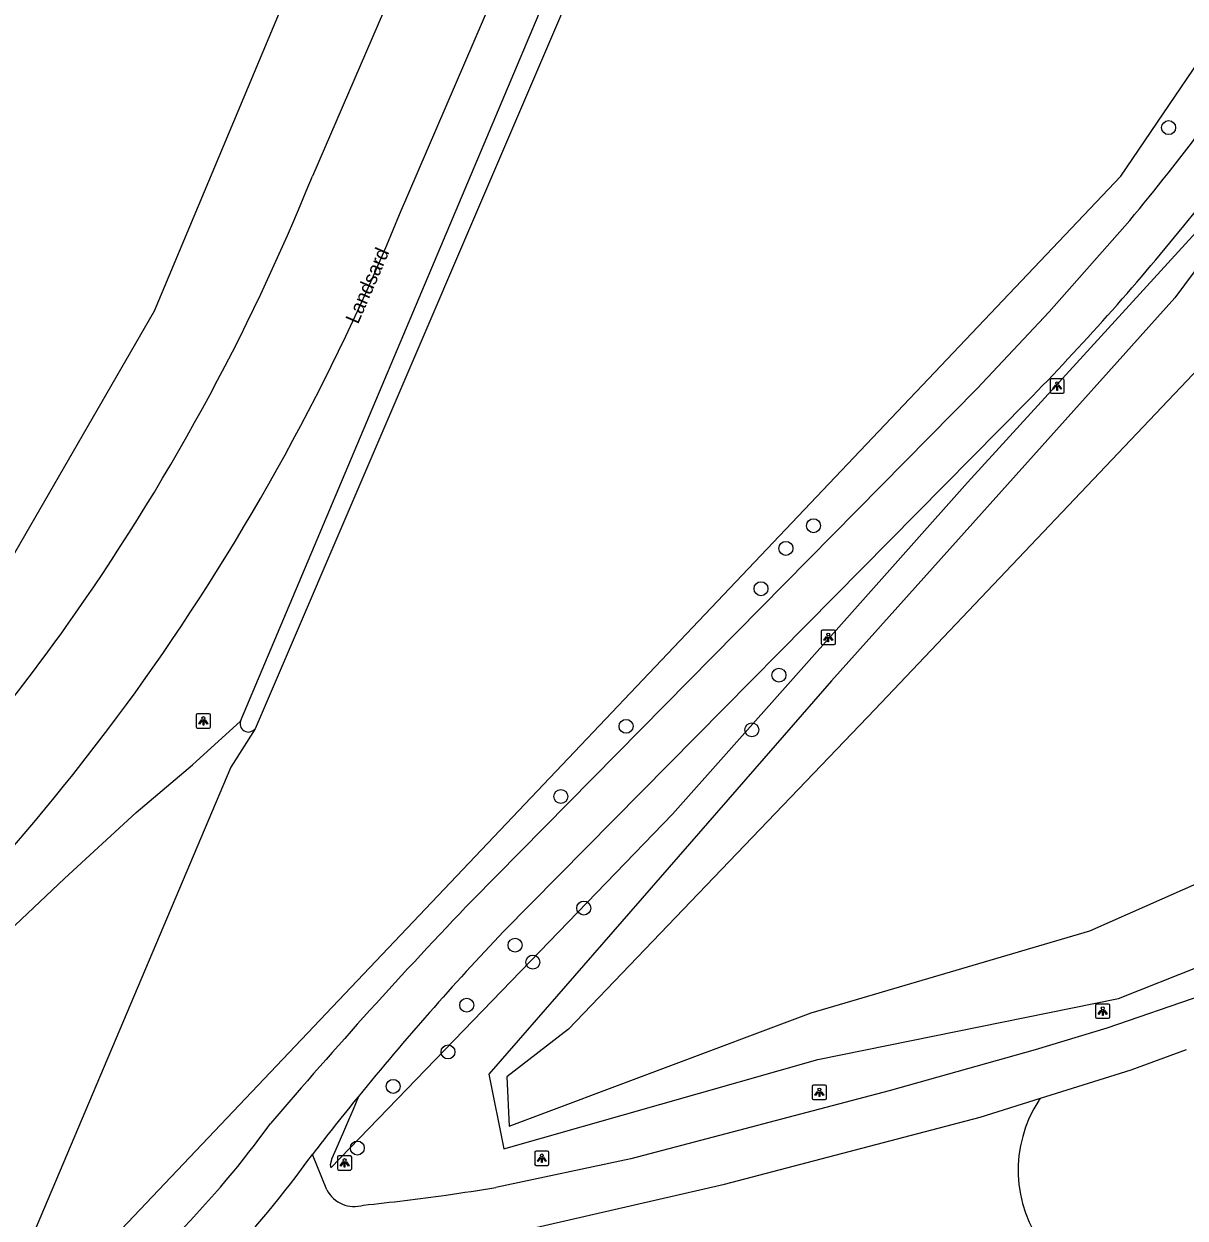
# Model space of a CAD drawing. Extents: x 155209 to 156823, y 385356 to 388482.
# Drawn here: x 155855.7 to 155937, y 385809.7 to 385893.3 of the extents above; entities that cross this region are included whole.
import ezdxf

# ---------------------------------------------------------------- set-up
doc = ezdxf.new("R2010")
doc.units = 0
for name, color, linetype in [('IMGEO_Berm_groen', 7, 'Continuous'), ('IMGEO_Boom', 7, 'Continuous'), ('IMGEO_Fietspad_gesloten', 7, 'Continuous'), ('IMGEO_Gemengd_bos', 7, 'Continuous'), ('IMGEO_Groenvoorziening', 7, 'Continuous'), ('IMGEO_Lichtpunt', 7, 'Continuous'), ('IMGEO_Meer_plas_ven_vijver', 7, 'Continuous'), ('IMGEO_Openbare_ruimte_label', 7, 'Continuous'), ('IMGEO_Rijbaan_lokaal_gesloten', 7, 'Continuous'), ('IMGEO_Voetpad_gesloten', 7, 'Continuous'), ('IMGEO_Waterloop', 7, 'Continuous')]:
    doc.layers.add(name, color=color, linetype=linetype)

msp = doc.modelspace()

# ---------------------------------------------------------------- linework, layer by layer
at = {"layer": 'IMGEO_Berm_groen'}
for points in [[(155912.875, 385986.207), (155891.584, 385937.043), (155864.833, 385873.201), (155853.128, 385852.94), (155810.491, 385814.255)], [(155851.64, 385797.46), (155932.5, 385882.64), (155974.754, 385944.878)], [(155879.138, 385818.21), (155878.761, 385817.288), (155878.446, 385816.541), (155878.095, 385815.729), (155877.542, 385814.495), (155877.266, 385813.848), (155877.158, 385813.41), (155877.205, 385813.205), (155901.117, 385837.978), (155921.768, 385861.187), (155942.453, 385883.841), (155948.49, 385892.599), (155963.233, 385915.282), (155979.151, 385938.711)]]:
    msp.add_lwpolyline(points, dxfattribs=at)
at = {"layer": 'IMGEO_Boom'}
for centre in [(155935.858, 385886.043), (155910.998, 385858.168), (155909.063, 385856.581), (155907.318, 385853.758), (155908.575, 385847.699), (155897.871, 385844.121), (155906.676, 385843.871), (155893.306, 385839.208), (155894.908, 385831.395), (155890.1, 385828.798), (155891.34, 385827.613), (155886.714, 385824.599), (155885.405, 385821.32), (155881.565, 385818.91), (155879.058, 385814.591)]:
    msp.add_circle(centre, 0.489, dxfattribs=at)
at = {"layer": 'IMGEO_Fietspad_gesloten'}
for points in [[(155933.141, 385879.54), (155927.488, 385873.153), (155922.459, 385867.783), (155887.111, 385831.956)], [(155889.293, 385829.761), (155925.96, 385866.867)]]:
    msp.add_lwpolyline(points, dxfattribs=at)
for centre, radius, start, end in [((155776.139, 386009.099), 203.556, 320.47045, 325.2588), ((155816.957, 385978.333), 155.642, 320.42192, 326.01192), ((155802.683, 385987.718), 172.634, 315.5693, 321.03944), ((156157.898, 385573.198), 374.541, 136.30132, 139.52582), ((156039.362, 385687.589), 206.721, 136.54794, 140.81176), ((156023.94, 385699.941), 186.963, 140.75915, 142.35172), ((155818.09, 385855.945), 67.705, 307.10906, 324.17353), ((155820.492, 385853.717), 68.097, 307.27808, 324.46586)]:
    msp.add_arc(centre, radius, start, end, dxfattribs=at)
at = {"layer": 'IMGEO_Gemengd_bos'}
for points in [[(155783.189, 385764.802), (155786.452, 385768.755), (155814.49, 385793.571), (155841.441, 385817.507), (155847.372, 385823.232), (155851.615, 385826.935), (155858.565, 385833.471), (155863.57, 385838.094), (155867.526, 385841.417), (155870.87, 385844.477)], [(155871.899, 385843.955), (155870.192, 385841.27), (155853.466, 385801.772)]]:
    msp.add_lwpolyline(points, dxfattribs=at)
at = {"layer": 'IMGEO_Groenvoorziening'}
for points in [[(155888.261, 385819.766), (155889.317, 385814.546), (155911.288, 385820.799), (155932.355, 385825.067), (155949.646, 385831.927), (155967.557, 385842.808), (155981.858, 385856.223), (155994.392, 385870.487), (156007.087, 385887.004), (156010.242, 385891.845), (156009.128, 385895.281), (155991.836, 385915.751), (155977.796, 385930.252), (155955.115, 385899.464), (155936.283, 385874.129), (155912.245, 385847.299), (155888.261, 385819.766)], [(155926.885, 385818.084), (155926.778, 385817.932)]]:
    msp.add_lwpolyline(points, dxfattribs=at)
for centre, radius, start, end in [((155934.165, 385813.062), 8.897, 244.03812, 60.4661), ((155934.257, 385813.045), 8.934, 146.84109, 217.45408)]:
    msp.add_arc(centre, radius, start, end, dxfattribs=at)
at = {"layer": 'IMGEO_Lichtpunt'}
for p, q in [((155927.555, 385868.35), (155927.555, 385867.543)), ((155927.555, 385868.35), (155927.555, 385867.543)), ((155928.457, 385868.445), (155927.649, 385868.445)), ((155928.457, 385868.445), (155927.649, 385868.445)), ((155928.551, 385867.543), (155928.551, 385868.35)), ((155928.551, 385867.543), (155928.551, 385868.35)), ((155927.649, 385867.449), (155928.457, 385867.449)), ((155927.649, 385867.449), (155928.457, 385867.449)), ((155911.532, 385850.753), (155911.532, 385849.946)), ((155911.532, 385850.753), (155911.532, 385849.946)), ((155912.434, 385850.848), (155911.626, 385850.848)), ((155912.434, 385850.848), (155911.626, 385850.848)), ((155912.528, 385849.946), (155912.528, 385850.753)), ((155912.528, 385849.946), (155912.528, 385850.753)), ((155911.626, 385849.852), (155912.434, 385849.852)), ((155911.626, 385849.852), (155912.434, 385849.852)), ((155867.778, 385844.902), (155867.778, 385844.095)), ((155867.778, 385844.902), (155867.778, 385844.095)), ((155868.68, 385844.997), (155867.872, 385844.997)), ((155868.68, 385844.997), (155867.872, 385844.997)), ((155868.774, 385844.095), (155868.774, 385844.902)), ((155868.774, 385844.095), (155868.774, 385844.902)), ((155867.872, 385844.001), (155868.68, 385844.001)), ((155867.872, 385844.001), (155868.68, 385844.001)), ((155930.742, 385824.576), (155930.742, 385823.769)), ((155930.742, 385824.576), (155930.742, 385823.769)), ((155931.644, 385824.671), (155930.836, 385824.671)), ((155931.644, 385824.671), (155930.836, 385824.671)), ((155931.738, 385823.769), (155931.738, 385824.576)), ((155931.738, 385823.769), (155931.738, 385824.576)), ((155930.836, 385823.675), (155931.644, 385823.675)), ((155930.836, 385823.675), (155931.644, 385823.675)), ((155911.808, 385818.992), (155911, 385818.992)), ((155911.808, 385818.992), (155911, 385818.992)), ((155910.906, 385818.897), (155910.906, 385818.09)), ((155910.906, 385818.897), (155910.906, 385818.09)), ((155911.902, 385818.09), (155911.902, 385818.897)), ((155911.902, 385818.09), (155911.902, 385818.897)), ((155911, 385817.996), (155911.808, 385817.996)), ((155911, 385817.996), (155911.808, 385817.996)), ((155877.667, 385813.953), (155877.667, 385813.146)), ((155877.667, 385813.953), (155877.667, 385813.146)), ((155878.569, 385814.048), (155877.761, 385814.048)), ((155878.569, 385814.048), (155877.761, 385814.048)), ((155878.663, 385813.146), (155878.663, 385813.953)), ((155878.663, 385813.146), (155878.663, 385813.953)), ((155891.473, 385814.281), (155891.473, 385813.474)), ((155891.473, 385814.281), (155891.473, 385813.474)), ((155892.375, 385814.376), (155891.567, 385814.376)), ((155892.375, 385814.376), (155891.567, 385814.376)), ((155892.469, 385813.474), (155892.469, 385814.281)), ((155892.469, 385813.474), (155892.469, 385814.281)), ((155891.567, 385813.38), (155892.375, 385813.38)), ((155891.567, 385813.38), (155892.375, 385813.38)), ((155877.761, 385813.052), (155878.569, 385813.052)), ((155877.761, 385813.052), (155878.569, 385813.052))]:
    msp.add_line(p, q, dxfattribs=at)
for points in [[(155927.929, 385868.014), (155927.968, 385867.986), (155927.78, 385867.724), (155927.742, 385867.751), (155927.929, 385868.014)], [(155928.031, 385867.966), (155928.078, 385867.966), (155928.078, 385867.644), (155928.031, 385867.644), (155928.031, 385867.966)], [(155928.141, 385867.986), (155928.179, 385868.013), (155928.366, 385867.751), (155928.327, 385867.723), (155928.141, 385867.986)], [(155911.906, 385850.417), (155911.945, 385850.389), (155911.757, 385850.127), (155911.719, 385850.154), (155911.906, 385850.417)], [(155912.008, 385850.369), (155912.055, 385850.369), (155912.055, 385850.047), (155912.008, 385850.047), (155912.008, 385850.369)], [(155912.118, 385850.389), (155912.156, 385850.416), (155912.343, 385850.154), (155912.304, 385850.126), (155912.118, 385850.389)], [(155868.152, 385844.566), (155868.191, 385844.538), (155868.003, 385844.276), (155867.965, 385844.303), (155868.152, 385844.566)], [(155868.254, 385844.518), (155868.301, 385844.518), (155868.301, 385844.196), (155868.254, 385844.196), (155868.254, 385844.518)], [(155868.364, 385844.538), (155868.402, 385844.565), (155868.589, 385844.303), (155868.55, 385844.275), (155868.364, 385844.538)], [(155931.116, 385824.24), (155931.155, 385824.212), (155930.967, 385823.95), (155930.929, 385823.977), (155931.116, 385824.24)], [(155931.218, 385824.192), (155931.265, 385824.192), (155931.265, 385823.87), (155931.218, 385823.87), (155931.218, 385824.192)], [(155931.328, 385824.212), (155931.366, 385824.239), (155931.553, 385823.977), (155931.514, 385823.949), (155931.328, 385824.212)], [(155911.28, 385818.561), (155911.319, 385818.533), (155911.131, 385818.271), (155911.093, 385818.298), (155911.28, 385818.561)], [(155911.382, 385818.513), (155911.429, 385818.513), (155911.429, 385818.191), (155911.382, 385818.191), (155911.382, 385818.513)], [(155911.492, 385818.533), (155911.53, 385818.56), (155911.717, 385818.298), (155911.678, 385818.27), (155911.492, 385818.533)], [(155891.847, 385813.945), (155891.886, 385813.917), (155891.698, 385813.655), (155891.66, 385813.682), (155891.847, 385813.945)], [(155892.059, 385813.917), (155892.097, 385813.944), (155892.284, 385813.682), (155892.245, 385813.654), (155892.059, 385813.917)], [(155878.041, 385813.617), (155878.08, 385813.589), (155877.892, 385813.327), (155877.854, 385813.354), (155878.041, 385813.617)], [(155878.143, 385813.569), (155878.19, 385813.569), (155878.19, 385813.247), (155878.143, 385813.247), (155878.143, 385813.569)], [(155878.253, 385813.589), (155878.291, 385813.616), (155878.478, 385813.354), (155878.439, 385813.326), (155878.253, 385813.589)], [(155891.949, 385813.897), (155891.996, 385813.897), (155891.996, 385813.575), (155891.949, 385813.575), (155891.949, 385813.897)]]:
    msp.add_lwpolyline(points, dxfattribs=at)
for centre in [(155928.054, 385868.148), (155912.031, 385850.551), (155868.277, 385844.7), (155931.241, 385824.374), (155911.405, 385818.695), (155891.972, 385814.079), (155878.166, 385813.751)]:
    msp.add_circle(centre, 0.0994, dxfattribs=at)
for centre, start, end in [((155927.649, 385868.35), 90, 180), ((155927.649, 385868.35), 90, 180), ((155928.457, 385868.35), 0, 90), ((155928.457, 385868.35), 0, 90), ((155927.649, 385867.543), 180, 270), ((155927.649, 385867.543), 180, 270), ((155928.457, 385867.543), 270, 0), ((155928.457, 385867.543), 270, 360), ((155911.626, 385850.753), 90, 180), ((155911.626, 385850.753), 90, 180), ((155912.434, 385850.753), 0, 90), ((155912.434, 385850.753), 0, 90), ((155911.626, 385849.946), 180, 270), ((155911.626, 385849.946), 180, 270), ((155912.434, 385849.946), 270, 0), ((155912.434, 385849.946), 270, 360), ((155867.872, 385844.902), 90, 180), ((155867.872, 385844.902), 90, 180), ((155868.68, 385844.902), 0, 90), ((155868.68, 385844.902), 0, 90), ((155867.872, 385844.095), 180, 270), ((155867.872, 385844.095), 180, 270), ((155868.68, 385844.095), 270, 0), ((155868.68, 385844.095), 270, 360), ((155930.836, 385824.576), 90, 180), ((155930.836, 385824.576), 90, 180), ((155931.644, 385824.576), 0, 90), ((155931.644, 385824.576), 0, 90), ((155930.836, 385823.769), 180, 270), ((155930.836, 385823.769), 180, 270), ((155931.644, 385823.769), 270, 0), ((155931.644, 385823.769), 270, 360), ((155911, 385818.897), 90, 180), ((155911, 385818.897), 90, 180), ((155911.808, 385818.897), 0, 90), ((155911.808, 385818.897), 0, 90), ((155911, 385818.09), 180, 270), ((155911, 385818.09), 180, 270), ((155911.808, 385818.09), 270, 0), ((155911.808, 385818.09), 270, 360), ((155877.761, 385813.953), 90, 180), ((155877.761, 385813.953), 90, 180), ((155878.569, 385813.953), 0, 90), ((155878.569, 385813.953), 0, 90), ((155891.567, 385814.281), 90, 180), ((155891.567, 385814.281), 90, 180), ((155892.375, 385814.281), 0, 90), ((155892.375, 385814.281), 0, 90), ((155877.761, 385813.146), 180, 270), ((155877.761, 385813.146), 180, 270), ((155878.569, 385813.146), 270, 0), ((155878.569, 385813.146), 270, 360), ((155891.567, 385813.474), 180, 270), ((155891.567, 385813.474), 180, 270), ((155892.375, 385813.474), 270, 0), ((155892.375, 385813.474), 270, 360)]:
    msp.add_arc(centre, 0.0946, start, end, dxfattribs=at)
at = {"layer": 'IMGEO_Meer_plas_ven_vijver'}
msp.add_lwpolyline([(155889.535, 385819.584), (155889.685, 385816.12), (155910.825, 385824.069), (155930.33, 385829.808), (155946.962, 385837.145), (155963.611, 385846.601), (155978.457, 385860.054), (155988.816, 385873.26), (156004.399, 385893.657), (155989.286, 385913.133), (155978.691, 385926.605), (155958.315, 385895.998), (155940.196, 385871.532), (155915.277, 385845.306), (155893.832, 385822.916), (155889.535, 385819.584)], dxfattribs=at)
at = {"layer": 'IMGEO_Rijbaan_lokaal_gesloten'}
for points in [[(155882.018, 385879.971), (155929.137, 385989.377)], [(155908.982, 385959.227), (155875.912, 385882.637)]]:
    msp.add_lwpolyline(points, dxfattribs=at)
for centre, radius, start, end in [((155732.315, 385940.672), 154.881, 324.67295, 337.99387), ((155731.43, 385941.365), 162.622, 324.66521, 337.81953), ((155736.627, 385938.137), 149.898, 316.86832, 324.51049), ((155736.118, 385938.57), 157.182, 312.48657, 324.50826)]:
    msp.add_arc(centre, radius, start, end, dxfattribs=at)
at = {"layer": 'IMGEO_Voetpad_gesloten'}
for points in [[(155943.978, 385827.601), (155938.187, 385825.268), (155931.525, 385822.984), (155926.512, 385821.461), (155916.296, 385818.605), (155898.212, 385813.847), (155888.765, 385811.838)], [(155926.885, 385818.084), (155933.241, 385820.074), (155937.104, 385821.483)], [(155889.073, 385804.076), (155889.011, 385808.445), (155904.759, 385812.063), (155922.652, 385816.758), (155926.885, 385818.084)], [(155876.922, 385811.661), (155875.907, 385814.14)]]:
    msp.add_lwpolyline(points, dxfattribs=at)
for centre, radius, start, end in [((155878.841, 385812.664), 2.165, 207.60147, 287.12061), ((155864.76, 385955.739), 145.89, 278.08871, 279.47047), ((155865.094, 385953.226), 143.355, 275.75862, 278.098)]:
    msp.add_arc(centre, radius, start, end, dxfattribs=at)
at = {"layer": 'IMGEO_Waterloop'}
for points in [[(155870.87, 385844.477), (155910.3, 385937.905), (155931.883, 385987.977)], [(155933.29, 385987.259), (155871.899, 385843.955)]]:
    msp.add_lwpolyline(points, dxfattribs=at)
for centre, radius, start, end in [((155871.431, 385844.307), 0.586, 163.17737, 251.39762), ((155871.43, 385844.309), 0.588, 251.52571, 322.91318)]:
    msp.add_arc(centre, radius, start, end, dxfattribs=at)

# ---------------------------------------------------------------- texts
at = {"layer": 'IMGEO_Openbare_ruimte_label'}
msp.add_text('Landsard', height=1, rotation=66.61336, dxfattribs=at).set_placement((155879.103, 385872.233))

doc.saveas('drawing.dxf')
